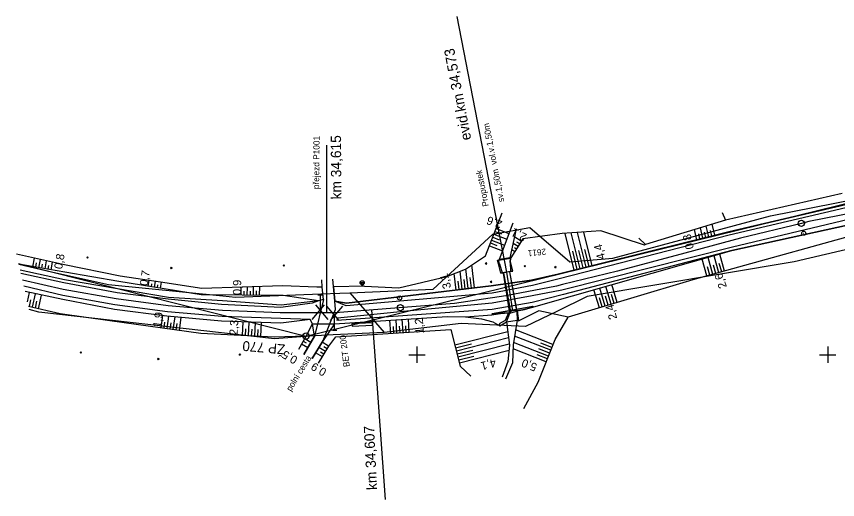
# Model space of a CAD drawing. Extents: x -805730 to -804640, y -1150889 to -1150366.
# Drawn here: x -805497.5 to -805297.6, y -1150735.2 to -1150617.7 of the extents above; entities that cross this region are included whole.
import ezdxf

# ---------------------------------------------------------------- set-up
doc = ezdxf.new("R2010")
doc.units = 0
for name, color, linetype in [('0381KM032-037P - Vrstva 1', 7, 'Continuous'), ('0381KM032-037P - Vrstva 17', 7, 'Continuous'), ('0381KM032-037P - Vrstva 19', 7, 'Continuous'), ('0381KM032-037P - Vrstva 36', 7, 'Continuous'), ('0381KM032-037P - Vrstva 4', 7, 'Continuous'), ('0381KM032-037P - Vrstva 48', 7, 'Continuous'), ('0381KM032-037P - Vrstva 49', 7, 'Continuous'), ('0381KM032-037P - Vrstva 51', 7, 'Continuous'), ('0381KM032-037P - Vrstva 55', 7, 'Continuous'), ('0381KM032-037P - Vrstva 57', 7, 'Continuous'), ('0381KM032-037P - Vrstva 7', 7, 'Continuous'), ('0381KM032-037P - Vrstva 9', 7, 'Continuous'), ('hran DP - hran DP', 7, 'Continuous'), ('krizky_1000 - Vrstva 1', 7, 'Continuous'), ('vyt_sit - polygon', 7, 'Continuous'), ('vyt_sit - stávající', 7, 'Continuous')]:
    doc.layers.add(name, color=color, linetype=linetype)

msp = doc.modelspace()

# ---------------------------------------------------------------- linework, layer by layer
at = {"layer": '0381KM032-037P - Vrstva 1'}
for points in [[(-805262.34, -1150660.99), (-805275.34, -1150662.5), (-805288.75, -1150664.54), (-805289.64, -1150664.68), (-805304.6, -1150667.62), (-805306.42, -1150668.06)], [(-805306.42, -1150668.06), (-805321.24, -1150671.67), (-805334.8, -1150675.29), (-805351.21, -1150679.7), (-805364.56, -1150682.93)], [(-805364.56, -1150682.93), (-805366.04, -1150683.29), (-805378.36, -1150685.71), (-805390.91, -1150687.55), (-805419.96, -1150689.78), (-805423.96, -1150689.8), (-805433.29, -1150689.8), (-805447.38, -1150689.21), (-805460.61, -1150688.07), (-805473.24, -1150686.41), (-805486.12, -1150684.11), (-805496.07, -1150681.84)]]:
    msp.add_lwpolyline(points, dxfattribs=at)
at = {"layer": '0381KM032-037P - Vrstva 17'}
msp.add_lwpolyline([(-805325.7, -1150665.45), (-805324.89, -1150667.28), (-805344.39, -1150673.21), (-805345.97, -1150671.67)], dxfattribs=at)
at = {"layer": '0381KM032-037P - Vrstva 19'}
for p, q in [((-805378.12, -1150679.9), (-805390.23, -1150617.73)), ((-805380.17, -1150676.97), (-805377.25, -1150676.53)), ((-805377.12, -1150676.41), (-805377.25, -1150676.53)), ((-805377.23, -1150677.51), (-805377.12, -1150676.41)), ((-805380.42, -1150677), (-805380.17, -1150676.97)), ((-805380.12, -1150677.92), (-805380.42, -1150677)), ((-805378.95, -1150680.08), (-805377.25, -1150689.53)), ((-805377.4, -1150689.87), (-805378.93, -1150680.13)), ((-805378.22, -1150679.93), (-805376.73, -1150689.34)), ((-805377.44, -1150679.8), (-805375.79, -1150689.3)), ((-805377.44, -1150679.84), (-805375.71, -1150689.44)), ((-805371.83, -1150688.19), (-805372.13, -1150688.5)), ((-805381.67, -1150690), (-805381.78, -1150690.33)), ((-805425.41, -1150692.47), (-805420.07, -1150692.47)), ((-805378.2, -1150692.01), (-805375.64, -1150691.6))]:
    msp.add_line(p, q, dxfattribs=at)
for points in [[(-805379.92, -1150677.91), (-805380.17, -1150676.97), (-805380.03, -1150676.88), (-805377.35, -1150676.44)], [(-805377.3, -1150677.55), (-805377.25, -1150676.53), (-805377.35, -1150676.44)], [(-805379.6, -1150680.17), (-805380.12, -1150677.92), (-805379.92, -1150677.91), (-805379.23, -1150680.09)], [(-805377.44, -1150679.8), (-805377.44, -1150679.84), (-805377.2, -1150679.71), (-805376.64, -1150679.64), (-805377.23, -1150677.51), (-805377.3, -1150677.55), (-805377.2, -1150679.71)], [(-805376.64, -1150679.64), (-805379.6, -1150680.17), (-805379.23, -1150680.09), (-805378.93, -1150680.13), (-805378.95, -1150680.08)], [(-805377.25, -1150689.53), (-805377.4, -1150689.87), (-805377.71, -1150689.8), (-805379.64, -1150689.94), (-805381.78, -1150690.33), (-805381.61, -1150690.16), (-805381.67, -1150690), (-805371.83, -1150688.19), (-805371.8, -1150688.29), (-805381.61, -1150690.16)], [(-805371.8, -1150688.29), (-805372.13, -1150688.5), (-805373.84, -1150688.99), (-805375.5, -1150689.3), (-805375.71, -1150689.44), (-805375.79, -1150689.3)], [(-805377.71, -1150689.8), (-805378.52, -1150691.68), (-805379.98, -1150692.52), (-805379.86, -1150692.97), (-805378.2, -1150692.01), (-805377.4, -1150689.87)], [(-805375.71, -1150689.44), (-805375.64, -1150691.6), (-805375.2, -1150691.74), (-805375.5, -1150689.3)]]:
    msp.add_lwpolyline(points, dxfattribs=at)
for centre, major_axis, ratio, start_param, end_param in [((-805378.2, -1150679.95), (-0.792, -0.149), 0.032025, 3.416243, 5.97224), ((-805376.52, -1150689.46), (-0.761, -0.129), 0.198559, 3.38498, 5.924926)]:
    msp.add_ellipse(centre, major_axis=major_axis, ratio=ratio, start_param=start_param, end_param=end_param, dxfattribs=at)
at = {"layer": '0381KM032-037P - Vrstva 36'}
for p, q in [((-805413.84, -1150682.5), (-805412.84, -1150682.5)), ((-805412.84, -1150682.5), (-805413.84, -1150682.5)), ((-805413.28, -1150683), (-805413.77, -1150682.5)), ((-805412.94, -1150682.8), (-805413.24, -1150682.5))]:
    msp.add_line(p, q, dxfattribs=at)
msp.add_circle((-805413.34, -1150682.5), 0.503, dxfattribs=at)
msp.add_arc((-805413.34, -1150682.5), 0.503, 180, 0, dxfattribs=at)
at = {"layer": '0381KM032-037P - Vrstva 4'}
for p, q in [((-805421.99, -1150689.77), (-805421.99, -1150649.07)), ((-805423.11, -1150685.55), (-805424.11, -1150685.55)), ((-805423.61, -1150685.55), (-805423.61, -1150689.05)), ((-805422.61, -1150687.9), (-805425.61, -1150691.4)), ((-805421.61, -1150691.4), (-805424.61, -1150687.9)), ((-805422.05, -1150688.15), (-805419.05, -1150691.65)), ((-805421.05, -1150691.65), (-805418.05, -1150688.15)), ((-805423.96, -1150689.8), (-805419.82, -1150689.74)), ((-805420.05, -1150694), (-805420.05, -1150690.5)), ((-805420.55, -1150694), (-805419.55, -1150694))]:
    msp.add_line(p, q, dxfattribs=at)
for points in [[(-805228.99, -1150656.61), (-805257.13, -1150657.62), (-805260.23, -1150658.03), (-805264.49, -1150659.11), (-805283.86, -1150661.58), (-805295.64, -1150663.5), (-805324.06, -1150670.09), (-805365.63, -1150680.4), (-805372.09, -1150681.89), (-805381.91, -1150683.24), (-805417.14, -1150687.42), (-805420, -1150686.97)], [(-805212.28, -1150657.22), (-805228.89, -1150657.63), (-805258.88, -1150659.27), (-805264.46, -1150659.8), (-805283.61, -1150662.28), (-805295.6, -1150664.3), (-805323.97, -1150670.91), (-805365.39, -1150681.52), (-805371.9, -1150683.14), (-805381.67, -1150685.01), (-805417.27, -1150688.09), (-805420, -1150686.97)], [(-805212.01, -1150660.08), (-805229.13, -1150661), (-805258.58, -1150662.1), (-805264.18, -1150662.62), (-805283.43, -1150665.36), (-805294.93, -1150667.11), (-805323.21, -1150673.86), (-805364.72, -1150684.28), (-805371.95, -1150685.67), (-805381.73, -1150687.49), (-805401.63, -1150689.36), (-805419.33, -1150691.07), (-805419.49, -1150691.68)], [(-805225.57, -1150661.42), (-805229.16, -1150661.68), (-805258.55, -1150662.93), (-805264.16, -1150663.27), (-805283.37, -1150665.88), (-805323.33, -1150674.68), (-805364.37, -1150685.33), (-805371.95, -1150687.26), (-805381.71, -1150688.97), (-805419.49, -1150691.68)], [(-805485.85, -1150681.76), (-805496.62, -1150679.43)], [(-805423.97, -1150686.92), (-805425.51, -1150687.49), (-805433.17, -1150688.49), (-805447.58, -1150687.79), (-805460.54, -1150686.52), (-805473.03, -1150684.97), (-805486, -1150682.53), (-805496.44, -1150680.22)], [(-805423.97, -1150686.92), (-805433.1, -1150687.91), (-805447.34, -1150686.91), (-805460.49, -1150686.09), (-805485.85, -1150681.76)], [(-805425.98, -1150691.47), (-805433.13, -1150691.22), (-805447.47, -1150690.71), (-805460.74, -1150689.57), (-805473.54, -1150687.87), (-805486.2, -1150685.62), (-805495.72, -1150683.36)], [(-805425.41, -1150692.47), (-805425.98, -1150691.47), (-805433.11, -1150692.35), (-805447.61, -1150691.82), (-805460.9, -1150690.59), (-805473.67, -1150688.98), (-805486.26, -1150686.57), (-805495.43, -1150684.63)]]:
    msp.add_lwpolyline(points, dxfattribs=at)
at = {"layer": '0381KM032-037P - Vrstva 48'}
for p, q in [((-805327.47, -1150670.94), (-805328.14, -1150668.27)), ((-805381.03, -1150670.01), (-805379.45, -1150670.62)), ((-805380.75, -1150669.31), (-805377.62, -1150670.53)), ((-805361.74, -1150679.43), (-805363.95, -1150670.5)), ((-805360.28, -1150679.07), (-805362.44, -1150670.39)), ((-805358.83, -1150678.71), (-805360.92, -1150670.29)), ((-805357.37, -1150678.35), (-805359.4, -1150670.18)), ((-805331.84, -1150672.02), (-805332.45, -1150669.58)), ((-805331.11, -1150671.84), (-805331.42, -1150670.6)), ((-805330.39, -1150671.66), (-805331.01, -1150669.14)), ((-805329.66, -1150671.48), (-805329.97, -1150670.2)), ((-805328.93, -1150671.3), (-805329.57, -1150668.7)), ((-805328.2, -1150671.12), (-805328.53, -1150669.8)), ((-805381.84, -1150672.11), (-805378.68, -1150673.33)), ((-805381.57, -1150671.41), (-805379.99, -1150672.02)), ((-805381.3, -1150670.71), (-805378.15, -1150671.93)), ((-805374.6, -1150672.41), (-805376.2, -1150671.41)), ((-805375, -1150673.05), (-805375.68, -1150672.61)), ((-805382.38, -1150673.51), (-805379.21, -1150674.74)), ((-805382.11, -1150672.81), (-805380.53, -1150673.42)), ((-805376.2, -1150674.95), (-805376.9, -1150674.5)), ((-805375.4, -1150673.68), (-805376.55, -1150672.96)), ((-805375.8, -1150674.31), (-805376.26, -1150674.02)), ((-805359.56, -1150678.89), (-805360.62, -1150674.62)), ((-805358.1, -1150678.53), (-805359.13, -1150674.38)), ((-805493.52, -1150678.6), (-805493.15, -1150676.49)), ((-805361.01, -1150679.25), (-805362.1, -1150674.85)), ((-805327.99, -1150680.45), (-805329.14, -1150676.32)), ((-805326.55, -1150680.05), (-805327.69, -1150675.91)), ((-805325.1, -1150679.65), (-805326.25, -1150675.51)), ((-805492.78, -1150678.73), (-805492.6, -1150677.69)), ((-805492.04, -1150678.85), (-805491.69, -1150676.82)), ((-805491.3, -1150678.98), (-805491.13, -1150677.99)), ((-805490.56, -1150679.11), (-805490.22, -1150677.16)), ((-805489.82, -1150679.23), (-805489.66, -1150678.28)), ((-805489.08, -1150679.36), (-805488.76, -1150677.49)), ((-805386.02, -1150683.73), (-805386.68, -1150678.15)), ((-805329.44, -1150680.85), (-805330.58, -1150676.73)), ((-805328.71, -1150680.65), (-805329.29, -1150678.59)), ((-805327.27, -1150680.25), (-805327.84, -1150678.19)), ((-805325.82, -1150679.85), (-805326.4, -1150677.78)), ((-805390.49, -1150684.26), (-805390.96, -1150680.28)), ((-805389, -1150684.08), (-805389.52, -1150679.69)), ((-805387.51, -1150683.91), (-805388.09, -1150679.07)), ((-805465.41, -1150683.34), (-805465.19, -1150681.94)), ((-805463.93, -1150683.58), (-805463.7, -1150682.16)), ((-805462.45, -1150683.82), (-805462.22, -1150682.37)), ((-805389.75, -1150684.17), (-805389.99, -1150682.08)), ((-805388.26, -1150684), (-805388.53, -1150681.7)), ((-805386.77, -1150683.82), (-805387.08, -1150681.21)), ((-805464.67, -1150683.46), (-805464.56, -1150682.75)), ((-805463.19, -1150683.7), (-805463.07, -1150682.98)), ((-805442.82, -1150685.49), (-805442.8, -1150683.6)), ((-805442.07, -1150685.49), (-805442.06, -1150684.53)), ((-805441.32, -1150685.5), (-805441.3, -1150683.55)), ((-805440.57, -1150685.5), (-805440.56, -1150684.52)), ((-805439.82, -1150685.51), (-805439.8, -1150683.51)), ((-805439.07, -1150685.51), (-805439.06, -1150684.5)), ((-805438.32, -1150685.52), (-805438.3, -1150683.46)), ((-805355.6, -1150688.59), (-805356.92, -1150684.19)), ((-805354.17, -1150688.16), (-805355.47, -1150683.78)), ((-805352.73, -1150687.73), (-805354.03, -1150683.37)), ((-805351.29, -1150687.3), (-805352.58, -1150682.96)), ((-805494.86, -1150687.12), (-805494.33, -1150684.87)), ((-805493.64, -1150688.47), (-805492.86, -1150685.18)), ((-805492.18, -1150688.82), (-805491.39, -1150685.49)), ((-805354.89, -1150688.37), (-805355.54, -1150686.18)), ((-805353.45, -1150687.94), (-805354.1, -1150685.76)), ((-805352.01, -1150687.52), (-805352.66, -1150685.34)), ((-805494.37, -1150688.3), (-805493.98, -1150686.66)), ((-805492.91, -1150688.64), (-805492.52, -1150686.99)), ((-805462.31, -1150693.46), (-805461.89, -1150690.47)), ((-805461.56, -1150693.56), (-805461.35, -1150692.06)), ((-805460.82, -1150693.66), (-805460.4, -1150690.64)), ((-805460.08, -1150693.77), (-805459.86, -1150692.24)), ((-805459.33, -1150693.87), (-805458.91, -1150690.78)), ((-805458.59, -1150693.97), (-805458.38, -1150692.41)), ((-805457.85, -1150694.07), (-805457.41, -1150690.91)), ((-805442.5, -1150695.34), (-805442.32, -1150692.01)), ((-805441, -1150695.43), (-805440.82, -1150692.07)), ((-805439.5, -1150695.51), (-805439.32, -1150692.12)), ((-805438, -1150695.59), (-805437.82, -1150692.18)), ((-805406.38, -1150694.81), (-805406.59, -1150691.59)), ((-805404.88, -1150694.71), (-805405.09, -1150691.49)), ((-805403.39, -1150694.62), (-805403.59, -1150691.39)), ((-805401.89, -1150694.52), (-805402.09, -1150691.3)), ((-805441.75, -1150695.39), (-805441.66, -1150693.71)), ((-805440.25, -1150695.47), (-805440.16, -1150693.78)), ((-805438.75, -1150695.55), (-805438.66, -1150693.85)), ((-805405.63, -1150694.76), (-805405.73, -1150693.15)), ((-805404.13, -1150694.66), (-805404.24, -1150693.05)), ((-805402.64, -1150694.57), (-805402.74, -1150692.96)), ((-805390.77, -1150697.63), (-805377.9, -1150694.34)), ((-805366.89, -1150697.51), (-805376.01, -1150693.96)), ((-805427.34, -1150696.06), (-805425.83, -1150696.92)), ((-805390.4, -1150699.08), (-805377.71, -1150695.84)), ((-805367.43, -1150698.91), (-805376.24, -1150695.48)), ((-805428.08, -1150697.36), (-805426.58, -1150698.22)), ((-805427.71, -1150696.71), (-805426.96, -1150697.14)), ((-805422.27, -1150699.19), (-805423.9, -1150698.22)), ((-805421.51, -1150697.9), (-805423.11, -1150696.95)), ((-805421.89, -1150698.54), (-805422.7, -1150698.06)), ((-805390.59, -1150698.36), (-805386.75, -1150697.38)), ((-805390.03, -1150700.54), (-805377.53, -1150697.34)), ((-805368.52, -1150701.71), (-805376.62, -1150698.55)), ((-805367.98, -1150700.31), (-805376.48, -1150697)), ((-805367.71, -1150699.61), (-805370.3, -1150698.6)), ((-805367.16, -1150698.21), (-805369.85, -1150697.16)), ((-805423.04, -1150700.48), (-805424.68, -1150699.5)), ((-805422.66, -1150699.83), (-805423.47, -1150699.35)), ((-805390.21, -1150699.81), (-805386.44, -1150698.85)), ((-805389.84, -1150701.27), (-805386.15, -1150700.32)), ((-805389.66, -1150701.99), (-805377.59, -1150698.91)), ((-805368.25, -1150701.01), (-805370.75, -1150700.03))]:
    msp.add_line(p, q, dxfattribs=at)
at = {"layer": '0381KM032-037P - Vrstva 49'}
for p, q in [((-805383.32, -1150675.93), (-805379.28, -1150665.5)), ((-805376.67, -1150668.04), (-805380.03, -1150676.88)), ((-805377.35, -1150676.44), (-805375.74, -1150669.42)), ((-805374.21, -1150671.8), (-805377.12, -1150676.41)), ((-805480.06, -1150676.54), (-805480.41, -1150676.19)), ((-805480.06, -1150676.19), (-805480.41, -1150676.54)), ((-805377.35, -1150676.44), (-805380.03, -1150676.88)), ((-805377.12, -1150676.41), (-805377.35, -1150676.44)), ((-805432.26, -1150678.45), (-805432.61, -1150678.1)), ((-805432.26, -1150678.1), (-805432.61, -1150678.45)), ((-805383.03, -1150677.64), (-805383.38, -1150678)), ((-805383.38, -1150677.64), (-805383.02, -1150678)), ((-805373.92, -1150678.26), (-805373.56, -1150678.61)), ((-805373.56, -1150678.26), (-805373.91, -1150678.61)), ((-805366.14, -1150678.54), (-805366.49, -1150678.89)), ((-805366.49, -1150678.54), (-805366.13, -1150678.89)), ((-805459.62, -1150679.12), (-805459.97, -1150678.77)), ((-805459.62, -1150678.77), (-805459.97, -1150679.12)), ((-805381.8, -1150682.09), (-805382.15, -1150682.45)), ((-805382.15, -1150682.09), (-805381.8, -1150682.44)), ((-805426.99, -1150695.45), (-805425.41, -1150692.47)), ((-805481.65, -1150699.61), (-805482, -1150699.26)), ((-805481.65, -1150699.26), (-805482, -1150699.61)), ((-805442.98, -1150700.16), (-805443.33, -1150699.81)), ((-805442.98, -1150699.81), (-805443.33, -1150700.16)), ((-805462.79, -1150701.28), (-805463.14, -1150700.93)), ((-805462.79, -1150700.93), (-805463.14, -1150701.28))]:
    msp.add_line(p, q, dxfattribs=at)
for points in [[(-805420, -1150686.97), (-805417.14, -1150687.42), (-805381.91, -1150683.24), (-805372.09, -1150681.89), (-805365.63, -1150680.4), (-805324.06, -1150670.09), (-805295.64, -1150663.5), (-805283.86, -1150661.58), (-805264.49, -1150659.11)], [(-805372.13, -1150688.5), (-805323.33, -1150674.68), (-805283.37, -1150665.88), (-805264.16, -1150663.27), (-805258.55, -1150662.93), (-805229.16, -1150661.68), (-805225.47, -1150661.83)], [(-805296.52, -1150660.78), (-805324.89, -1150667.28), (-805344.39, -1150673.21)], [(-805229.52, -1150663.36), (-805258.94, -1150664.75), (-805264.69, -1150666.1), (-805283.13, -1150668.03), (-805332.88, -1150681.81), (-805363.18, -1150690.85)], [(-805344.39, -1150673.21), (-805344.61, -1150673.34), (-805355.22, -1150669.89), (-805364.63, -1150670.55), (-805374.21, -1150671.8)], [(-805424.36, -1150683.57), (-805432.74, -1150683.28), (-805452.35, -1150683.91), (-805462.43, -1150682.34), (-805472.3, -1150680.9), (-805485.84, -1150678.15), (-805497.52, -1150675.51)], [(-805412.74, -1150683.31), (-805404.41, -1150683.71), (-805392.74, -1150681.01), (-805388.23, -1150679.16), (-805383.32, -1150675.93)], [(-805422.8, -1150686.53), (-805423.97, -1150686.92), (-805432.55, -1150685.56), (-805452.56, -1150685.41), (-805472.6, -1150682.19), (-805485.72, -1150679.94), (-805496.95, -1150678.01)], [(-805423.97, -1150686.92), (-805433.1, -1150687.91), (-805447.34, -1150686.91), (-805460.49, -1150686.09), (-805485.85, -1150681.76), (-805496.62, -1150679.43)], [(-805422.8, -1150686.53), (-805423.05, -1150683.54), (-805424.36, -1150683.57)], [(-805412.74, -1150683.31), (-805420.31, -1150683.48), (-805420, -1150686.97)], [(-805425.41, -1150692.47), (-805425.98, -1150691.47), (-805433.11, -1150692.35), (-805447.61, -1150691.82), (-805460.9, -1150690.59), (-805473.67, -1150688.98), (-805486.26, -1150686.57), (-805495.43, -1150684.63)], [(-805428.8, -1150698.61), (-805426.99, -1150695.45), (-805434.79, -1150695.76), (-805452.59, -1150694.8), (-805474.79, -1150691.73), (-805486.9, -1150690.07), (-805494.61, -1150688.24)], [(-805420.07, -1150692.47), (-805392.63, -1150690.68), (-805388.18, -1150690.75), (-805381.78, -1150690.33), (-805379.64, -1150689.94), (-805377.71, -1150689.8), (-805377.4, -1150689.87), (-805375.71, -1150689.44), (-805375.5, -1150689.3), (-805373.84, -1150688.99), (-805372.13, -1150688.5)], [(-805363.18, -1150690.85), (-805370.35, -1150689.33), (-805375.2, -1150691.74), (-805375.64, -1150691.6)], [(-805427.56, -1150699.92), (-805424.99, -1150695.46), (-805425.41, -1150692.47)], [(-805420.07, -1150692.47), (-805422.84, -1150696.5), (-805425.52, -1150700.88)], [(-805388.18, -1150690.75), (-805384.32, -1150691.25), (-805381.55, -1150691.98), (-805379.86, -1150692.97), (-805378.2, -1150692.01), (-805377.48, -1150697.71), (-805377.85, -1150701.68), (-805379.27, -1150705.45)], [(-805378.2, -1150692.01), (-805375.64, -1150691.6), (-805376.57, -1150697.62), (-805376.78, -1150701.96), (-805378.44, -1150705.91)], [(-805374.03, -1150713.04), (-805370.47, -1150706.7), (-805366.4, -1150696.26), (-805363.18, -1150690.85)], [(-805419.74, -1150695.67), (-805391.73, -1150693.87), (-805389.46, -1150702.77), (-805386.92, -1150705.25)], [(-805423.96, -1150702.03), (-805421.5, -1150697.89), (-805419.74, -1150695.67)]]:
    msp.add_lwpolyline(points, dxfattribs=at)
at = {"layer": '0381KM032-037P - Vrstva 51'}
for points in [[(-805425.52, -1150700.88), (-805422.84, -1150696.5), (-805419.83, -1150688.97), (-805420, -1150686.97), (-805420.48, -1150681.6)], [(-805422.8, -1150686.53), (-805423.05, -1150683.54), (-805423.2, -1150681.79)], [(-805422.8, -1150686.53), (-805424.99, -1150695.46), (-805427.56, -1150699.92)]]:
    msp.add_lwpolyline(points, dxfattribs=at)
at = {"layer": '0381KM032-037P - Vrstva 55'}
msp.add_line((-805416.34, -1150684.94), (-805408.01, -1150694.56), dxfattribs=at)
at = {"layer": '0381KM032-037P - Vrstva 7'}
for p, q in [((-805305.9, -1150670.45), (-805305.8, -1150670.45)), ((-805404.26, -1150686.19), (-805404.16, -1150686.19))]:
    msp.add_line(p, q, dxfattribs=at)
for centre, radius in [((-805306.42, -1150668.06), 0.75), ((-805305.85, -1150670.45), 0.5), ((-805404.21, -1150686.19), 0.5), ((-805404.03, -1150688.55), 0.75)]:
    msp.add_circle(centre, radius, dxfattribs=at)
at = {"layer": '0381KM032-037P - Vrstva 9'}
for p, q in [((-805411.08, -1150689.08), (-805407.73, -1150735.22)), ((-805410.84, -1150692.23), (-805415.83, -1150692.47)), ((-805415.83, -1150692.47), (-805415.8, -1150693.06)), ((-805410.84, -1150692.23), (-805410.86, -1150691.64)), ((-805410.81, -1150692.82), (-805410.84, -1150692.23)), ((-805415.8, -1150693.06), (-805410.81, -1150692.82))]:
    msp.add_line(p, q, dxfattribs=at)
at = {"layer": 'hran DP - hran DP'}
for p, q in [((-805313.93, -1150666.21), (-805288.99, -1150661.29)), ((-805352.32, -1150676.52), (-805313.93, -1150666.21)), ((-805267.02, -1150667.87), (-805308.19, -1150677.39)), ((-805381.52, -1150670.67), (-805372.51, -1150669.03)), ((-805372.51, -1150669.03), (-805362.8, -1150677.38)), ((-805396.07, -1150684.02), (-805381.52, -1150670.67)), ((-805362.8, -1150677.38), (-805352.32, -1150676.52)), ((-805496.95, -1150678.01), (-805488.96, -1150679.81)), ((-805308.19, -1150677.39), (-805358.57, -1150685.85)), ((-805488.96, -1150679.81), (-805475.13, -1150682.93)), ((-805475.13, -1150682.93), (-805447.24, -1150685.68)), ((-805416.34, -1150684.94), (-805396.07, -1150684.02)), ((-805447.24, -1150685.68), (-805444.22, -1150685.98)), ((-805444.22, -1150685.98), (-805433.7, -1150685.59)), ((-805433.7, -1150685.59), (-805423.42, -1150685.2)), ((-805423.42, -1150685.2), (-805418.81, -1150685.03)), ((-805418.81, -1150685.03), (-805416.34, -1150684.94)), ((-805358.57, -1150685.85), (-805365.99, -1150689.46)), ((-805492.06, -1150689.65), (-805494.44, -1150688.97)), ((-805434.71, -1150696.14), (-805492.06, -1150689.65)), ((-805365.99, -1150689.46), (-805373.55, -1150693.14)), ((-805389.21, -1150692.42), (-805408.01, -1150694.56)), ((-805373.55, -1150693.14), (-805389.21, -1150692.42)), ((-805408.01, -1150694.56), (-805420.42, -1150695.2)), ((-805426.08, -1150695.49), (-805434.71, -1150696.14)), ((-805420.42, -1150695.2), (-805426.08, -1150695.49))]:
    msp.add_line(p, q, dxfattribs=at)
at = {"layer": 'krizky_1000 - Vrstva 1'}
for points in [[(-805400, -1150698), (-805400, -1150702)], [(-805300, -1150698), (-805300, -1150702)], [(-805402, -1150700), (-805398, -1150700)], [(-805302, -1150700), (-805298, -1150700)]]:
    msp.add_lwpolyline(points, dxfattribs=at)
at = {"layer": 'vyt_sit - polygon'}
for p, q in [((-805426.99, -1150695.45), (-805292.36, -1150662.43)), ((-805497, -1150677.79), (-805426.99, -1150695.45))]:
    msp.add_line(p, q, dxfattribs=at)
at = {"layer": 'vyt_sit - stávající'}
msp.add_line((-805427.04, -1150695.45), (-805426.94, -1150695.45), dxfattribs=at)
msp.add_circle((-805426.99, -1150695.45), 0.756, dxfattribs=at)

# ---------------------------------------------------------------- texts
at = {"layer": '0381KM032-037P - Vrstva 19'}
for s, height, rotation, p in [('evid.km 34,573', 2.5, 100.6945, (-805386.78, -1150647.62)), ('sv.1,50m  vol.v.1,50m', 1.4999, 101.0532, (-805378.75, -1150662.72)), ('Propustek', 1.5, 101.1547, (-805382.51, -1150663.81)), ('BET 200', 1.5, 97.5063, (-805416.36, -1150702.88))]:
    msp.add_text(s, height=height, rotation=rotation, dxfattribs=at).set_placement(p)
at = {"layer": '0381KM032-037P - Vrstva 4'}
for s, height, rotation, p in [('přejezd P1001', 1.5, 89.4547, (-805423.83, -1150659.74)), ('km 34,615', 2.5, 90.3142, (-805418.41, -1150662.22))]:
    msp.add_text(s, height=height, rotation=rotation, dxfattribs=at).set_placement(p)
at = {"layer": '0381KM032-037P - Vrstva 48'}
for s, height, rotation, p in [('2,6', 2, 158.8025, (-805379.08, -1150667.6)), ('2,1', 2, 154.4647, (-805373.08, -1150670.75)), ('0,8', 1.99, 103.9155, (-805332.56, -1150674.1)), ('4,4', 2, 103.9188, (-805354.16, -1150676.55)), ('0,8', 2, 80.2414, (-805486.4, -1150679.29)), ('0,7', 2, 80.8528, (-805465.58, -1150683.35)), ('3,1', 2, 104.8055, (-805391.65, -1150683.68)), ('2,6', 2, 109.5492, (-805324.53, -1150683.48)), ('0,9', 2, 89.5678, (-805442.82, -1150685.49)), ('2,4', 2, 105.8138, (-805351.25, -1150691.15)), ('1,9', 2, 82.1252, (-805462.31, -1150693.46)), ('2,3', 2, 86.8943, (-805443.69, -1150695.28)), ('1,2', 2, 93.6817, (-805398.33, -1150694.8)), ('0,5', 2, 150.2278, (-805428.88, -1150700.69)), ('0,9', 2, 149.2587, (-805421.83, -1150703.66)), ('4,1', 2, 194.3297, (-805381.04, -1150700.95)), ('5,0', 2, 158.7077, (-805370.58, -1150702.28))]:
    msp.add_text(s, height=height, rotation=rotation, dxfattribs=at).set_placement(p)
at = {"layer": '0381KM032-037P - Vrstva 51'}
msp.add_text('polní cesta', height=1.5, rotation=58.5387, dxfattribs=at).set_placement((-805430.69, -1150709.03))
at = {"layer": '0381KM032-037P - Vrstva 57'}
msp.add_text('2611', height=1.5, rotation=185.7179, dxfattribs=at).set_placement((-805368.65, -1150674.18))
at = {"layer": '0381KM032-037P - Vrstva 9'}
msp.add_text('km 34,607', height=2.5, rotation=92.7706, dxfattribs=at).set_placement((-805409.71, -1150732.84))
at = {"layer": 'vyt_sit - stávající'}
msp.add_text('ŽP 770', height=2.4, rotation=175, dxfattribs=at).set_placement((-805432.05, -1150697.54))

doc.saveas('drawing.dxf')
